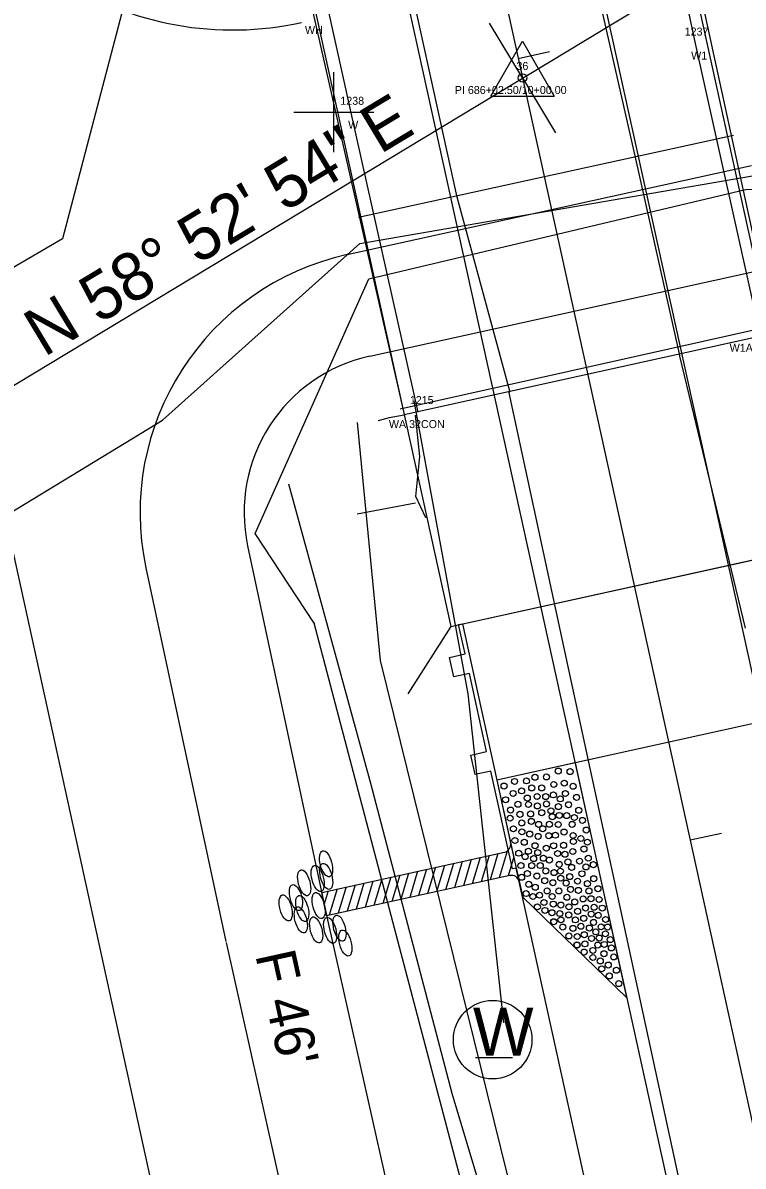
# Model space of a CAD drawing. Extents: x 2519952 to 2531965, y 848341 to 887632.
# Drawn here: x 2524424.7 to 2524514.7, y 869788.7 to 869931.6 of the extents above; entities that cross this region are included whole.
import ezdxf

# ---------------------------------------------------------------- set-up
doc = ezdxf.new("R2010")
doc.units = 0
for name, color, linetype in [('RD_EV_JW', 7, 'Continuous'), ('RD_EX_BldgApp', 7, 'Continuous'), ('RD_EX_BldgApp_txCode', 7, 'Continuous'), ('RD_EX_Bridge', 7, 'Continuous'), ('RD_EX_Conc', 7, 'Continuous'), ('RD_EX_DR_Pipe', 7, 'Continuous'), ('RD_EX_DV_Prop', 7, 'Continuous'), ('RD_EX_GuardRail', 7, 'Continuous'), ('RD_EX_H2O', 7, 'Continuous'), ('RD_EX_Misc', 7, 'Continuous'), ('RD_EX_Road', 7, 'Continuous'), ('RD_EX_RW', 7, 'Continuous'), ('RD_EX_UT', 7, 'Continuous'), ('RD_EX_VEG', 7, 'Continuous'), ('RD_HC_Cl', 7, 'Continuous'), ('RD_HC_Data', 7, 'Continuous'), ('RD_HC_Data_Tic', 7, 'Continuous'), ('RD_HC_txCode', 7, 'Continuous'), ('RD_PD_BCA', 7, 'Continuous'), ('RD_PD_Bridge', 7, 'Continuous'), ('RD_PD_CstnLmt', 7, 'Continuous'), ('RD_PD_DR_ErosCtrl', 7, 'Continuous'), ('RD_PD_Final_TrvlWay', 7, 'Continuous'), ('RD_PD_GR', 7, 'Continuous'), ('RD_PD_PaveShd', 7, 'Continuous'), ('RD_SMD_Locator', 7, 'Continuous')]:
    doc.layers.add(name, color=color, linetype=linetype)

# ---------------------------------------------------------------- blocks, each defined once
blk = doc.blocks.new('TBC1')
at = {"layer": 'RD_PD_GR'}
blk.add_lwpolyline([(12.5, 2.5), (15, 2.5), (15, 0.49), (25, 0.49), (25, 2.5), (27.5, 2.5), (27.5, 0.49), (31.25, 0.49), (31.25, 0), (0, 0), (0, 0.49), (12.5, 0.49)], close=True, dxfattribs=at)

msp = doc.modelspace()

# ---------------------------------------------------------------- linework, layer by layer
at = {"layer": 'RD_EV_JW'}
msp.add_lwpolyline([(2524525.2, 869274.67), (2524564.88, 869322.7), (2524583.4, 869339.87), (2524580.23, 869387.75), (2524545.19, 869541.45), (2524520.38, 869638.82), (2524501.71, 869719.92), (2524478.36, 869797.79), (2524468.19, 869836.51), (2524457.95, 869873.93)], dxfattribs=at)
at = {"layer": 'RD_EX_BldgApp'}
for points in [[(2524516.89, 869892.47), (2524508.77, 869928.99), (2524500.76, 869966.53)], [(2524474.13, 869882.94), (2524465.73, 869920.34), (2524457.66, 869956.92)]]:
    msp.add_lwpolyline(points, dxfattribs=at)
at = {"layer": 'RD_EX_Bridge'}
for points in [[(2524472.36, 869882.63), (2524518.65, 869892.86), (2524502.52, 869966.92), (2524455.6, 869956.47), (2524472.36, 869882.63)], [(2524472.35, 869882.57), (2524470.47, 869882.24), (2524469.12, 869881.83)]]:
    msp.add_lwpolyline(points, dxfattribs=at)
at = {"layer": 'RD_EX_Conc'}
msp.add_lwpolyline([(2524475.06, 869869.74), (2524473.82, 869872.39), (2524474.33, 869877.37), (2524473.78, 869882.57)], dxfattribs=at)
at = {"layer": 'RD_EX_DR_Pipe'}
msp.add_line((2524473.78, 869871.54), (2524466.49, 869870.17), dxfattribs=at)
at = {"layer": 'RD_EX_DV_Prop'}
msp.add_line((2524381.12, 870057.49), (2524445.63, 869764.51), dxfattribs=at)
at = {"layer": 'RD_EX_GuardRail'}
msp.add_lwpolyline([(2524484.83, 869806.61), (2524480.36, 869847.71), (2524473.61, 869884.33)], dxfattribs=at)
at = {"layer": 'RD_EX_H2O'}
for points in [[(2524280.27, 869571.37), (2524295.57, 869662.01), (2524325.04, 869706.78), (2524321.22, 869733.31), (2524284.03, 869760.46), (2524298.4, 869779.15), (2524330.51, 869802.71), (2524376.62, 869842.08), (2524442.17, 869881.92), (2524466.83, 869904.02), (2524522.92, 869913.69), (2524522.92, 869913.69), (2524542.69, 869915.86), (2524587.71, 869959.96)], [(2524439.21, 869940.95), (2524429.64, 869904.6), (2524362.35, 869865.29), (2524312.32, 869827.05), (2524256.4, 869777.66), (2524258.08, 869747.45), (2524187.46, 869716.79)], [(2524490.19, 869746.15), (2524461.13, 869856.58), (2524453.72, 869867.75), (2524467.93, 869899.58), (2524515.02, 869910.74), (2524525.28, 869911.03)]]:
    msp.add_lwpolyline(points, dxfattribs=at)
at = {"layer": 'RD_EX_Misc'}
for p, q in [((2524463.58, 869915.4), (2524463.58, 869925.4)), ((2524458.58, 869920.4), (2524468.58, 869920.4)), ((2524513.54, 869917.5), (2524466.66, 869907.25)), ((2524471.88, 869883.34), (2524518.8, 869893.81))]:
    msp.add_line(p, q, dxfattribs=at)
at = {"layer": 'RD_EX_Road'}
for p, q in [((2524501.25, 869914.97), (2524495.76, 869939.17)), ((2524478.97, 869909.8), (2524473.63, 869934.24)), ((2524506.77, 869890.22), (2524501.25, 869914.97)), ((2524485.59, 869885.57), (2524478.97, 869909.8)), ((2524506.83, 869889.91), (2524506.77, 869890.22)), ((2524515.03, 869855.95), (2524506.83, 869889.91)), ((2524485.5, 869885.34), (2524485.59, 869885.57)), ((2524492.92, 869850.93), (2524485.5, 869885.34)), ((2524514.45, 869751.33), (2524492.92, 869850.93))]:
    msp.add_line(p, q, dxfattribs=at)
at = {"layer": 'RD_EX_RW'}
msp.add_line((2524381.12, 870057.49), (2524445.63, 869764.51), dxfattribs=at)
at = {"layer": 'RD_EX_UT'}
msp.add_line((2524481.29, 869802.3), (2524485.92, 869802.3), dxfattribs=at)
msp.add_circle((2524483.42, 869804.51), 4.91, dxfattribs=at)
at = {"layer": 'RD_EX_VEG'}
msp.add_lwpolyline([(2524497.69, 869223.25), (2524589.7, 869304), (2524542.03, 869557.84), (2524469.4, 869851.91), (2524466.51, 869881.65)], dxfattribs=at)
at = {"layer": 'RD_HC_Cl'}
for p, q in [((2524338.62, 870599.23), (2524895.21, 868071.59)), ((2524369.5, 869853.66), (2524534.63, 869953.35))]:
    msp.add_line(p, q, dxfattribs=at)
at = {"layer": 'RD_HC_Data'}
for p, q in [((2524483.18, 869922.4), (2524487.16, 869929.28)), ((2524487.16, 869929.28), (2524491.13, 869922.4)), ((2524483.18, 869922.4), (2524491.13, 869922.4))]:
    msp.add_line(p, q, dxfattribs=at)
msp.add_circle((2524487.16, 869924.69), 0.529, dxfattribs=at)
at = {"layer": 'RD_HC_Data_Tic'}
for p, q in [((2524487.15, 869924.69), (2524483.01, 869931.53)), ((2524486.62, 869927.13), (2524490.52, 869927.99)), ((2524487.15, 869924.69), (2524491.28, 869917.84)), ((2524508.12, 869829.47), (2524512.03, 869830.33))]:
    msp.add_line(p, q, dxfattribs=at)
at = {"layer": 'RD_PD_BCA'}
msp.add_arc((2524450.91, 869970.69), 40, 192.0677, 282.4185, dxfattribs=at)
at = {"layer": 'RD_PD_Bridge'}
for p, q in [((2524478.18, 869856.16), (2524524.08, 869866.26)), ((2524479.65, 869856.48), (2524483.95, 869836.95)), ((2524478.18, 869856.16), (2524472.8, 869847.73)), ((2524526.92, 869846.41), (2524483.95, 869836.95))]:
    msp.add_line(p, q, dxfattribs=at)
for points in [[(2524524.08, 869866.26), (2524496.13, 869993.22)], [(2524450.23, 869983.12), (2524478.18, 869856.16)], [(2524478.18, 869856.16), (2524524.08, 869866.26)]]:
    msp.add_lwpolyline(points, dxfattribs=at)
at = {"layer": 'RD_PD_CstnLmt'}
for p, q in [((2524452.79, 869866.21), (2524462.78, 869819.48)), ((2524462.78, 869819.48), (2524484.63, 869721.9))]:
    msp.add_line(p, q, dxfattribs=at)
msp.add_lwpolyline([(2524468.05, 869889.93), (2524518.59, 869901.05)], dxfattribs=at)
msp.add_arc((2524472.35, 869870.39), 20, 102.4185, 192.0677, dxfattribs=at)
at = {"layer": 'RD_PD_DR_ErosCtrl'}
for p, q in [((2524440.08, 869863.49), (2524450.07, 869816.77)), ((2524450.09, 869816.64), (2524471.94, 869719.06))]:
    msp.add_line(p, q, dxfattribs=at)
msp.add_lwpolyline([(2524465.25, 869902.62), (2524515.79, 869913.75)], dxfattribs=at)
msp.add_arc((2524472.35, 869870.39), 33, 102.4185, 192.0677, dxfattribs=at)
at = {"layer": 'RD_PD_Final_TrvlWay'}
for p, q in [((2524439.2, 870198.28), (2524713.39, 868953.11)), ((2524415.76, 870193.11), (2524689.95, 868947.95))]:
    msp.add_line(p, q, dxfattribs=at)
at = {"layer": 'RD_PD_GR'}
msp.add_line((2524593.89, 869337.66), (2524486.37, 869825.96), dxfattribs=at)
at = {"layer": 'RD_PD_PaveShd'}
for p, q in [((2524493.72, 869839.1), (2524483.95, 869836.95)), ((2524493.72, 869839.1), (2524500.17, 869809.8)), ((2524483.95, 869836.95), (2524485.88, 869828.16)), ((2524462.05, 869822.92), (2524484.91, 869827.94)), ((2524485.23, 869828.08), (2524484.23, 869824.72)), ((2524485.88, 869828.16), (2524486.53, 869825.23)), ((2524478.51, 869826.54), (2524477.52, 869823.25)), ((2524478.51, 869826.54), (2524477.52, 869823.25)), ((2524479.63, 869826.78), (2524478.64, 869823.5)), ((2524479.63, 869826.78), (2524478.64, 869823.5)), ((2524480.74, 869827.03), (2524479.76, 869823.74)), ((2524481.86, 869827.27), (2524480.88, 869823.99)), ((2524481.86, 869827.27), (2524480.88, 869823.99)), ((2524482.98, 869827.52), (2524481.99, 869824.23)), ((2524482.98, 869827.52), (2524481.99, 869824.23)), ((2524484.09, 869827.77), (2524483.11, 869824.48)), ((2524484.09, 869827.77), (2524483.11, 869824.48)), ((2524486.06, 869827.36), (2524485.35, 869824.97)), ((2524485.55, 869825.01), (2524462.67, 869819.99)), ((2524471.8, 869825.07), (2524470.82, 869821.78)), ((2524471.8, 869825.07), (2524470.82, 869821.78)), ((2524472.92, 869825.31), (2524471.94, 869822.02)), ((2524472.92, 869825.31), (2524471.94, 869822.02)), ((2524474.04, 869825.56), (2524473.05, 869822.27)), ((2524474.04, 869825.56), (2524473.05, 869822.27)), ((2524475.16, 869825.8), (2524474.17, 869822.51)), ((2524475.16, 869825.8), (2524474.17, 869822.51)), ((2524476.27, 869826.05), (2524475.29, 869822.76)), ((2524476.27, 869826.05), (2524475.29, 869822.76)), ((2524477.39, 869826.29), (2524476.41, 869823)), ((2524477.39, 869826.29), (2524476.41, 869823)), ((2524486.53, 869825.23), (2524487.18, 869822.3)), ((2524465.1, 869823.59), (2524464.12, 869820.31)), ((2524465.1, 869823.59), (2524464.12, 869820.31)), ((2524466.22, 869823.84), (2524465.23, 869820.55)), ((2524466.22, 869823.84), (2524465.23, 869820.55)), ((2524467.34, 869824.08), (2524466.35, 869820.8)), ((2524467.34, 869824.08), (2524466.35, 869820.8)), ((2524468.45, 869824.33), (2524467.47, 869821.04)), ((2524468.45, 869824.33), (2524467.47, 869821.04)), ((2524469.57, 869824.57), (2524468.59, 869821.29)), ((2524469.57, 869824.57), (2524468.59, 869821.29)), ((2524470.69, 869824.82), (2524469.7, 869821.53)), ((2524470.69, 869824.82), (2524469.82, 869821.94)), ((2524462.67, 869819.99), (2524462.05, 869822.92)), ((2524462.87, 869823.1), (2524462.37, 869821.43)), ((2524463.98, 869823.35), (2524463, 869820.06)), ((2524463.98, 869823.35), (2524463.12, 869820.47)), ((2524500.17, 869809.8), (2524487.18, 869822.3))]:
    msp.add_line(p, q, dxfattribs=at)
for centre in [(2524491.63, 869838.08), (2524491.63, 869838.08), (2524493.1, 869838.01), (2524493.1, 869838.01), (2524484.85, 869836.2), (2524484.85, 869836.2), (2524484.85, 869836.2), (2524486.16, 869836.78), (2524486.16, 869836.78), (2524487.65, 869836.85), (2524487.65, 869836.85), (2524488.71, 869837.3), (2524488.71, 869837.3), (2524490.15, 869837.34), (2524490.15, 869837.34), (2524491.07, 869836.4), (2524491.07, 869836.4), (2524492.38, 869836.57), (2524492.38, 869836.57), (2524493.48, 869836.18), (2524493.48, 869836.18), (2524485.98, 869835.28), (2524485.98, 869835.28), (2524487.04, 869835.6), (2524487.04, 869835.6), (2524487.75, 869834.7), (2524487.75, 869834.7), (2524488.31, 869835.97), (2524488.31, 869835.97), (2524488.98, 869834.9), (2524488.98, 869834.9), (2524489.55, 869835.97), (2524489.55, 869835.97), (2524490.06, 869834.89), (2524490.06, 869834.89), (2524491.01, 869835.1), (2524491.01, 869835.1), (2524491.88, 869834.6), (2524491.88, 869834.6), (2524492.51, 869835.27), (2524492.51, 869835.27), (2524493.91, 869834.79), (2524493.91, 869834.79), (2524485.04, 869834.49), (2524485.04, 869834.49), (2524485.66, 869833.2), (2524485.66, 869833.2), (2524486.58, 869833.92), (2524486.58, 869833.92), (2524487.9, 869833.9), (2524487.9, 869833.9), (2524489.01, 869833.72), (2524489.01, 869833.72), (2524490.15, 869833.97), (2524490.15, 869833.97), (2524491.64, 869833.63), (2524491.64, 869833.63), (2524492.91, 869833.87), (2524492.91, 869833.87), (2524494.18, 869833.18), (2524494.18, 869833.18), (2524485.61, 869832.19), (2524485.61, 869832.19), (2524486.83, 869832.67), (2524486.83, 869832.67), (2524488.17, 869832.72), (2524488.17, 869832.72), (2524488.26, 869831.79), (2524488.26, 869831.79), (2524489.56, 869832.87), (2524489.56, 869832.87), (2524490.71, 869833.11), (2524490.88, 869832.37), (2524490.88, 869832.37), (2524491.75, 869832.53), (2524491.75, 869832.53), (2524492.68, 869832.51), (2524492.68, 869832.51), (2524493.64, 869832.27), (2524493.64, 869832.27), (2524494.65, 869831.92), (2524494.65, 869831.92), (2524486.02, 869830.86), (2524486.02, 869830.86), (2524487.07, 869831.59), (2524487.07, 869831.59), (2524487.09, 869830.48), (2524487.09, 869830.48), (2524489.17, 869831.41), (2524489.17, 869831.41), (2524489.68, 869830.87), (2524489.68, 869830.87), (2524490.51, 869831.43), (2524490.51, 869831.43), (2524491.62, 869831.4), (2524491.62, 869831.4), (2524492.35, 869830.46), (2524492.35, 869830.46), (2524493.36, 869831.42), (2524493.36, 869831.42), (2524495.12, 869830.71), (2524495.12, 869830.71), (2524486.21, 869829.4), (2524486.21, 869829.4), (2524487.38, 869829.18), (2524487.38, 869829.18), (2524488.06, 869830.21), (2524488.06, 869830.21), (2524489.11, 869829.92), (2524489.11, 869829.92), (2524490.44, 869830), (2524490.44, 869830), (2524491.26, 869830.06), (2524491.26, 869830.06), (2524493.48, 869830.02), (2524493.48, 869830.02), (2524493.51, 869829.27), (2524493.51, 869829.27), (2524494.45, 869829.65), (2524494.45, 869829.65), (2524495.26, 869829.19), (2524486.68, 869827.81), (2524486.68, 869827.81), (2524487.89, 869828.06), (2524487.89, 869828.06), (2524488.72, 869828.75), (2524488.72, 869828.75), (2524489.06, 869827.89), (2524489.06, 869827.89), (2524490.13, 869828.44), (2524490.13, 869828.44), (2524491.05, 869828.74), (2524491.05, 869828.74), (2524491.55, 869827.77), (2524491.55, 869827.77), (2524492.29, 869828.8), (2524492.29, 869828.8), (2524492.46, 869827.68), (2524492.46, 869827.68), (2524493.44, 869828.02), (2524493.44, 869828.02), (2524494.84, 869828.33), (2524494.84, 869828.33), (2524486.96, 869826.27), (2524486.96, 869826.27), (2524487.48, 869827.39), (2524487.48, 869827.39), (2524488.31, 869826.26), (2524488.31, 869826.26), (2524488.54, 869827.13), (2524488.54, 869827.13), (2524489.38, 869826.27), (2524489.38, 869826.27), (2524489.76, 869827.18), (2524489.76, 869827.18), (2524490.52, 869826.96), (2524490.52, 869826.96), (2524491.74, 869826.41), (2524491.74, 869826.41), (2524492.84, 869826.72), (2524492.84, 869826.72), (2524493.3, 869826.04), (2524493.3, 869826.04), (2524494.28, 869826.82), (2524494.28, 869826.82), (2524495.08, 869826.1), (2524495.08, 869826.1), (2524495.38, 869827.19), (2524495.38, 869827.19), (2524496.01, 869826.38), (2524496.01, 869826.38), (2524487.04, 869824.8), (2524487.04, 869824.8), (2524487.76, 869825.27), (2524487.76, 869825.27), (2524488.95, 869824.96), (2524488.95, 869824.96), (2524490.07, 869825.6), (2524490.07, 869825.6), (2524491.1, 869825.39), (2524491.1, 869825.39), (2524491.9, 869825.57), (2524491.9, 869825.57), (2524491.93, 869824.69), (2524491.93, 869824.69), (2524493.06, 869824.89), (2524493.06, 869824.89), (2524494.59, 869825.24), (2524494.59, 869825.24), (2524496.06, 869824.63), (2524496.06, 869824.63), (2524487.94, 869823.93), (2524487.94, 869823.93), (2524488.75, 869823.55), (2524488.75, 869823.55), (2524489.93, 869824.38), (2524489.93, 869824.38), (2524490.95, 869824.13), (2524490.95, 869824.13), (2524492.61, 869824.08), (2524492.61, 869824.08), (2524493.16, 869823.29), (2524493.16, 869823.29), (2524494.03, 869824.32), (2524494.03, 869824.32), (2524494.14, 869823.17), (2524494.14, 869823.17), (2524495.26, 869824.01), (2524495.26, 869824.01), (2524496.58, 869823.38), (2524496.58, 869823.38), (2524487.61, 869822.77), (2524487.61, 869822.77), (2524487.61, 869822.77), (2524488.45, 869822.4), (2524488.45, 869822.4), (2524489.28, 869822.56), (2524489.28, 869822.56), (2524490.23, 869823.1), (2524490.23, 869823.1), (2524490.87, 869822.4), (2524490.87, 869822.4), (2524491.7, 869823.1), (2524491.7, 869823.1), (2524492.7, 869822.3), (2524492.7, 869822.3), (2524493.68, 869821.72), (2524493.68, 869821.72), (2524494.73, 869822.1), (2524494.73, 869822.1), (2524495.46, 869823.09), (2524495.46, 869823.09), (2524495.71, 869822.12), (2524495.71, 869822.12), (2524496.73, 869822.03), (2524496.73, 869822.03), (2524489.02, 869821.11), (2524489.02, 869821.11), (2524489.84, 869821.65), (2524489.84, 869821.65), (2524489.96, 869820.66), (2524489.96, 869820.66), (2524490.84, 869820.38), (2524490.84, 869820.38), (2524491, 869821.45), (2524491, 869821.45), (2524491.82, 869820.27), (2524491.82, 869820.27), (2524491.95, 869821.33), (2524491.95, 869821.33), (2524492.96, 869821.11), (2524492.96, 869821.11), (2524494.05, 869820.56), (2524494.05, 869820.56), (2524495.03, 869820.96), (2524495.03, 869820.96), (2524496.11, 869821.05), (2524496.11, 869821.05), (2524497.13, 869820.95), (2524497.13, 869820.95), (2524491.06, 869819.25), (2524491.07, 869819.24), (2524491.96, 869819.49), (2524491.96, 869819.49), (2524492.93, 869820.1), (2524492.93, 869820.1), (2524493.76, 869819.48), (2524493.76, 869819.48), (2524494.81, 869819.67), (2524494.81, 869819.67), (2524495.74, 869820.2), (2524495.74, 869820.2), (2524496.03, 869819.17), (2524496.03, 869819.17), (2524496.62, 869820.05), (2524496.62, 869820.05), (2524497.54, 869819.53), (2524497.54, 869819.53), (2524492.19, 869818.59), (2524492.19, 869818.59), (2524492.95, 869817.47), (2524492.95, 869817.47), (2524493.46, 869818.42), (2524493.46, 869818.42), (2524494.45, 869818.68), (2524494.45, 869818.68), (2524494.88, 869817.62), (2524494.88, 869817.62), (2524495.52, 869818.46), (2524495.52, 869818.46), (2524496.32, 869817.98), (2524496.32, 869817.98), (2524496.98, 869818.61), (2524496.98, 869818.61), (2524497.52, 869817.74), (2524497.52, 869817.74), (2524497.78, 869818.58), (2524497.78, 869818.58), (2524493.95, 869816.35), (2524493.98, 869816.33), (2524493.99, 869817.4), (2524493.99, 869817.4), (2524494.96, 869816.48), (2524494.96, 869816.48), (2524495.78, 869817.16), (2524495.78, 869817.16), (2524496.57, 869816.33), (2524496.57, 869816.33), (2524496.74, 869817.21), (2524496.74, 869817.21), (2524497.38, 869816.41), (2524497.38, 869816.41), (2524498.12, 869817.01), (2524498.12, 869817.01), (2524494.86, 869815.46), (2524494.86, 869815.46), (2524495.95, 869815.66), (2524495.95, 869815.66), (2524495.95, 869814.78), (2524497.33, 869815.25), (2524497.33, 869815.25), (2524498.26, 869815.97), (2524498.26, 869815.97), (2524498.57, 869814.85), (2524498.57, 869814.85), (2524496.88, 869814.35), (2524496.88, 869814.35), (2524497.06, 869813.36), (2524497.06, 869813.36), (2524497.88, 869813.84), (2524497.88, 869813.84), (2524498.89, 869813.18), (2524498.89, 869813.18), (2524498, 869812.47), (2524498, 869812.47), (2524499.19, 869811.51)]:
    msp.add_circle(centre, 0.375, dxfattribs=at)
for centre, start, end in [((2524484.69, 869828.92), 282.3889, 12.4185), ((2524485.77, 869824.04), 12.4185, 102.3889)]:
    msp.add_arc(centre, 1, start, end, dxfattribs=at)
for centre in [(2524462.6, 869826.49), (2524462.6, 869826.49), (2524461.55, 869824.65), (2524461.55, 869824.65), (2524462.61, 869824.92), (2524462.61, 869824.92), (2524459.86, 869824.12), (2524459.86, 869824.12), (2524458.83, 869822.26), (2524458.83, 869822.26), (2524457.55, 869820.97), (2524457.55, 869820.97), (2524459.62, 869820.91), (2524459.62, 869820.91), (2524461.67, 869821.27), (2524461.67, 869821.27), (2524459.44, 869819.47), (2524459.44, 869819.47), (2524461.36, 869818.22), (2524461.36, 869818.22), (2524463.11, 869818.17), (2524463.11, 869818.17), (2524464.28, 869818.44), (2524465.01, 869816.59)]:
    msp.add_ellipse(centre, major_axis=(0.43, -1.62), ratio=0.429445, dxfattribs=at)
at = {"layer": 'RD_SMD_Locator'}
for centre in [(2524508.77, 869928.99), (2524487.16, 869924.69), (2524465.73, 869920.34), (2524513.54, 869917.5), (2524501.25, 869914.97), (2524478.97, 869909.8), (2524466.66, 869907.25), (2524429.64, 869904.6), (2524466.83, 869904.02), (2524467.93, 869899.58), (2524506.77, 869890.22), (2524506.83, 869889.91), (2524485.5, 869885.34), (2524485.59, 869885.57), (2524473.61, 869884.33), (2524470.47, 869882.24), (2524471.88, 869883.34), (2524472.35, 869882.57), (2524472.36, 869882.63), (2524472.36, 869882.63), (2524473.78, 869882.57), (2524474.13, 869882.94), (2524442.17, 869881.92), (2524466.51, 869881.65), (2524469.12, 869881.83), (2524474.33, 869877.37), (2524457.95, 869873.93), (2524473.82, 869872.39), (2524473.78, 869871.54), (2524466.49, 869870.17), (2524475.06, 869869.74), (2524453.72, 869867.75), (2524461.13, 869856.58), (2524469.4, 869851.91), (2524492.92, 869850.93), (2524480.36, 869847.71), (2524468.19, 869836.51), (2524472.79, 869818.39), (2524484.83, 869806.61), (2524478.36, 869797.79)]:
    msp.add_circle(centre, 0.001, dxfattribs=at)

# ---------------------------------------------------------------- block references
at = {"layer": 'RD_PD_Bridge', "rotation": 102.41848259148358}
msp.add_blockref('TBC1', (2524486.37, 869825.96), dxfattribs=at)

# ---------------------------------------------------------------- texts
at = {"layer": 'RD_EX_BldgApp_txCode'}
for s, p in [('WH', (2524459.96, 869930.19)), ('1237', (2524507.43, 869929.99)), ('W1', (2524508.24, 869926.99)), ('1238', (2524464.38, 869921.34)), ('W', (2524465.36, 869918.34)), ('W1A 32CON', (2524513.05, 869890.47)), ('1215', (2524473.07, 869883.94)), ('WA 32CON', (2524470.45, 869880.94))]:
    msp.add_text(s, height=1, dxfattribs=at).set_placement(p)
at = {"layer": 'RD_EX_UT'}
msp.add_text('W', height=6, dxfattribs=at).set_placement((2524480.96, 869802.51))
at = {"layer": 'RD_HC_Data'}
msp.add_text('N 58%%d 52\' 54" E', height=6, rotation=31.1184, dxfattribs=at).set_placement((2524427.33, 869889.74))
at = {"layer": 'RD_HC_txCode'}
for s, p in [('36', (2524486.4, 869925.69)), ('PI 686+02.50/10+00.00', (2524478.69, 869922.69))]:
    msp.add_text(s, height=1, dxfattribs=at).set_placement(p)
at = {"layer": 'RD_PD_CstnLmt'}
msp.add_text("F 46'", height=5, rotation=282.4185, dxfattribs=at).set_placement((2524453.73, 869815.11))

doc.saveas('drawing.dxf')
